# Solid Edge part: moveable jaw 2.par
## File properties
Author: CADSoft
Template: Normal.par
Last saved by: TIET
Revision: 6
Application: Solid Edge
Accuracy: 0.990
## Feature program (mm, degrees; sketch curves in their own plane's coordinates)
sketch for "unnamed Protrusion 1" plane through (0, 0, 0) normal (0, -1, 0) x-axis (1, 0, 0)
  line (2.077, -7.5) -> (2.077, 52.5)
  line (2.077, 52.5) -> (-32.423, 52.5)
  line (-32.423, 52.5) -> (-32.423, -7.5)
  line (-28.923, -7.5) -> (-32.423, -7.5)
  line (-28.923, -5) -> (-28.923, -7.5)
  line (-28.923, -5) -> (-26.423, -5)
  line (-26.423, -5) -> (-26.423, -2.5)
  line (-26.423, -2.5) -> (-23.923, -2.5)
  line (-23.923, -2.5) -> (-23.923, 0)
  line (-23.923, 0) -> (-21.423, 0)
  line (-21.423, 0) -> (-21.423, 2.5)
  line (-21.423, 2.5) -> (-18.923, 2.5)
  line (-18.923, 2.5) -> (-18.923, 5)
  line (-18.923, 5) -> (-16.423, 5)
  line (-16.423, 5) -> (-16.423, 7.5)
  line (-16.423, 7.5) -> (-15.173, 7.5)
  line (-13.923, 7.5) -> (-15.173, 7.5)
  line (-13.923, 5) -> (-13.923, 7.5)
  line (-11.423, 5) -> (-13.923, 5)
  line (-11.423, 2.5) -> (-11.423, 5)
  line (-8.923, 2.5) -> (-11.423, 2.5)
  line (-8.923, 0) -> (-8.923, 2.5)
  line (-6.423, 0) -> (-8.923, 0)
  line (-6.423, -2.5) -> (-6.423, 0)
  line (-3.923, -2.5) -> (-6.423, -2.5)
  line (-3.923, -5) -> (-3.923, -2.5)
  line (-1.423, -5) -> (-3.923, -5)
  line (-1.423, -5) -> (-1.423, -7.5)
  line (-1.423, -7.5) -> (2.077, -7.5)
extrude "unnamed Protrusion 1" add finite 18 symmetric
sketch for "Hole_1" plane through (-15.173, 0, 52.5) normal (0, 0, 1) x-axis (-1, 0, 0)
  hole centre (0, 0) bore radius 6
hole "Hole_1" diameter 12 finite  VBottomAngle = 120 deg
sketch for "Hole_2" plane through (2.077, 0, 22.5) normal (1, 0, 0) x-axis (0, 1, 0)
  hole centre (0, 23) bore radius 3
hole "Hole_2" diameter 6 through
chamfer "Chamfer_2" setback 2
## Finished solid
Body 1: solid body, 38 faces, 98 edges, 60 vertices.
  Faces by surface: plane 34, cylinder 3, cone 1
  Edges by curve: line 92, circle 4, intersection 2
Bounding box of the edges (mm): 34.500 x 18.000 x 60.000, from (-32.423, -9, -7.5) to (2.077, 9, 52.5).
Cylindrical faces by radius (mm): R3 x2, R6 x1
Conical faces (half-angle, radius in mm at the cone's reference point): 60 deg R6 x1
Planar faces by outward normal: +x 7, +y 1, +z 1, -x 7, -y 1, -z 13, oblique 4
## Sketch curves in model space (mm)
line (-26.423, 0, -5) -> (-26.423, 0, -2.5)
line (-26.423, 0, -2.5) -> (-23.923, 0, -2.5)
line (-23.923, 0, -2.5) -> (-23.923, 0, 0)
line (-23.923, 0, 0) -> (-21.423, 0, 0)
line (-21.423, 0, 0) -> (-21.423, 0, 2.5)
line (-21.423, 0, 2.5) -> (-18.923, 0, 2.5)
line (-18.923, 0, 2.5) -> (-18.923, 0, 5)
line (-18.923, 0, 5) -> (-16.423, 0, 5)
line (-16.423, 0, 5) -> (-16.423, 0, 7.5)
line (-16.423, 0, 7.5) -> (-15.173, 0, 7.5)
line (-13.923, 0, 7.5) -> (-15.173, 0, 7.5)
line (-13.923, 0, 5) -> (-13.923, 0, 7.5)
line (-11.423, 0, 5) -> (-13.923, 0, 5)
line (-11.423, 0, 2.5) -> (-11.423, 0, 5)
line (-8.923, 0, 2.5) -> (-11.423, 0, 2.5)
line (-8.923, 0, 0) -> (-8.923, 0, 2.5)
line (-6.423, 0, 0) -> (-8.923, 0, 0)
line (-6.423, 0, -2.5) -> (-6.423, 0, 0)
line (-3.923, 0, -2.5) -> (-6.423, 0, -2.5)
line (-3.923, 0, -5) -> (-3.923, 0, -2.5)
line (-1.423, 0, -5) -> (-3.923, 0, -5)
line (-1.423, 0, -5) -> (-1.423, 0, -7.5)
line (-1.423, 0, -7.5) -> (2.077, 0, -7.5)
line (2.077, 0, -7.5) -> (2.077, 0, 52.5)
line (2.077, 0, 52.5) -> (-32.423, 0, 52.5)
line (-32.423, 0, 52.5) -> (-32.423, 0, -7.5)
line (-28.923, 0, -7.5) -> (-32.423, 0, -7.5)
line (-28.923, 0, -5) -> (-28.923, 0, -7.5)
line (-28.923, 0, -5) -> (-26.423, 0, -5)
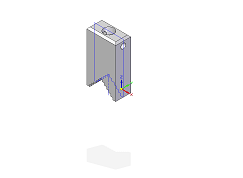
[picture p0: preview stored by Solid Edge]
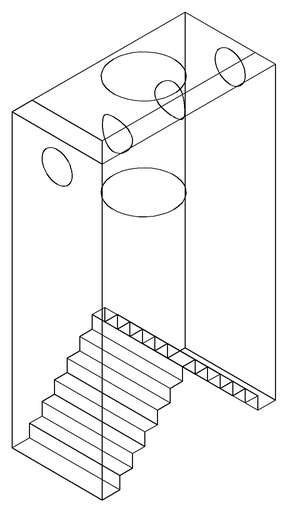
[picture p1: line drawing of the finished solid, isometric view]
